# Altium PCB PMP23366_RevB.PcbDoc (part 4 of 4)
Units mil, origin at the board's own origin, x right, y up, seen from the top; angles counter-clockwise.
Board outline 6500 x 4250 mil, 4 copper layers (Top Layer 1, Inner Layer 2, Inner Layer 3, Bottom Layer 1), stack 75.824 mil thick; 370 components, 218 nets, 1221 pads, 351 vias.
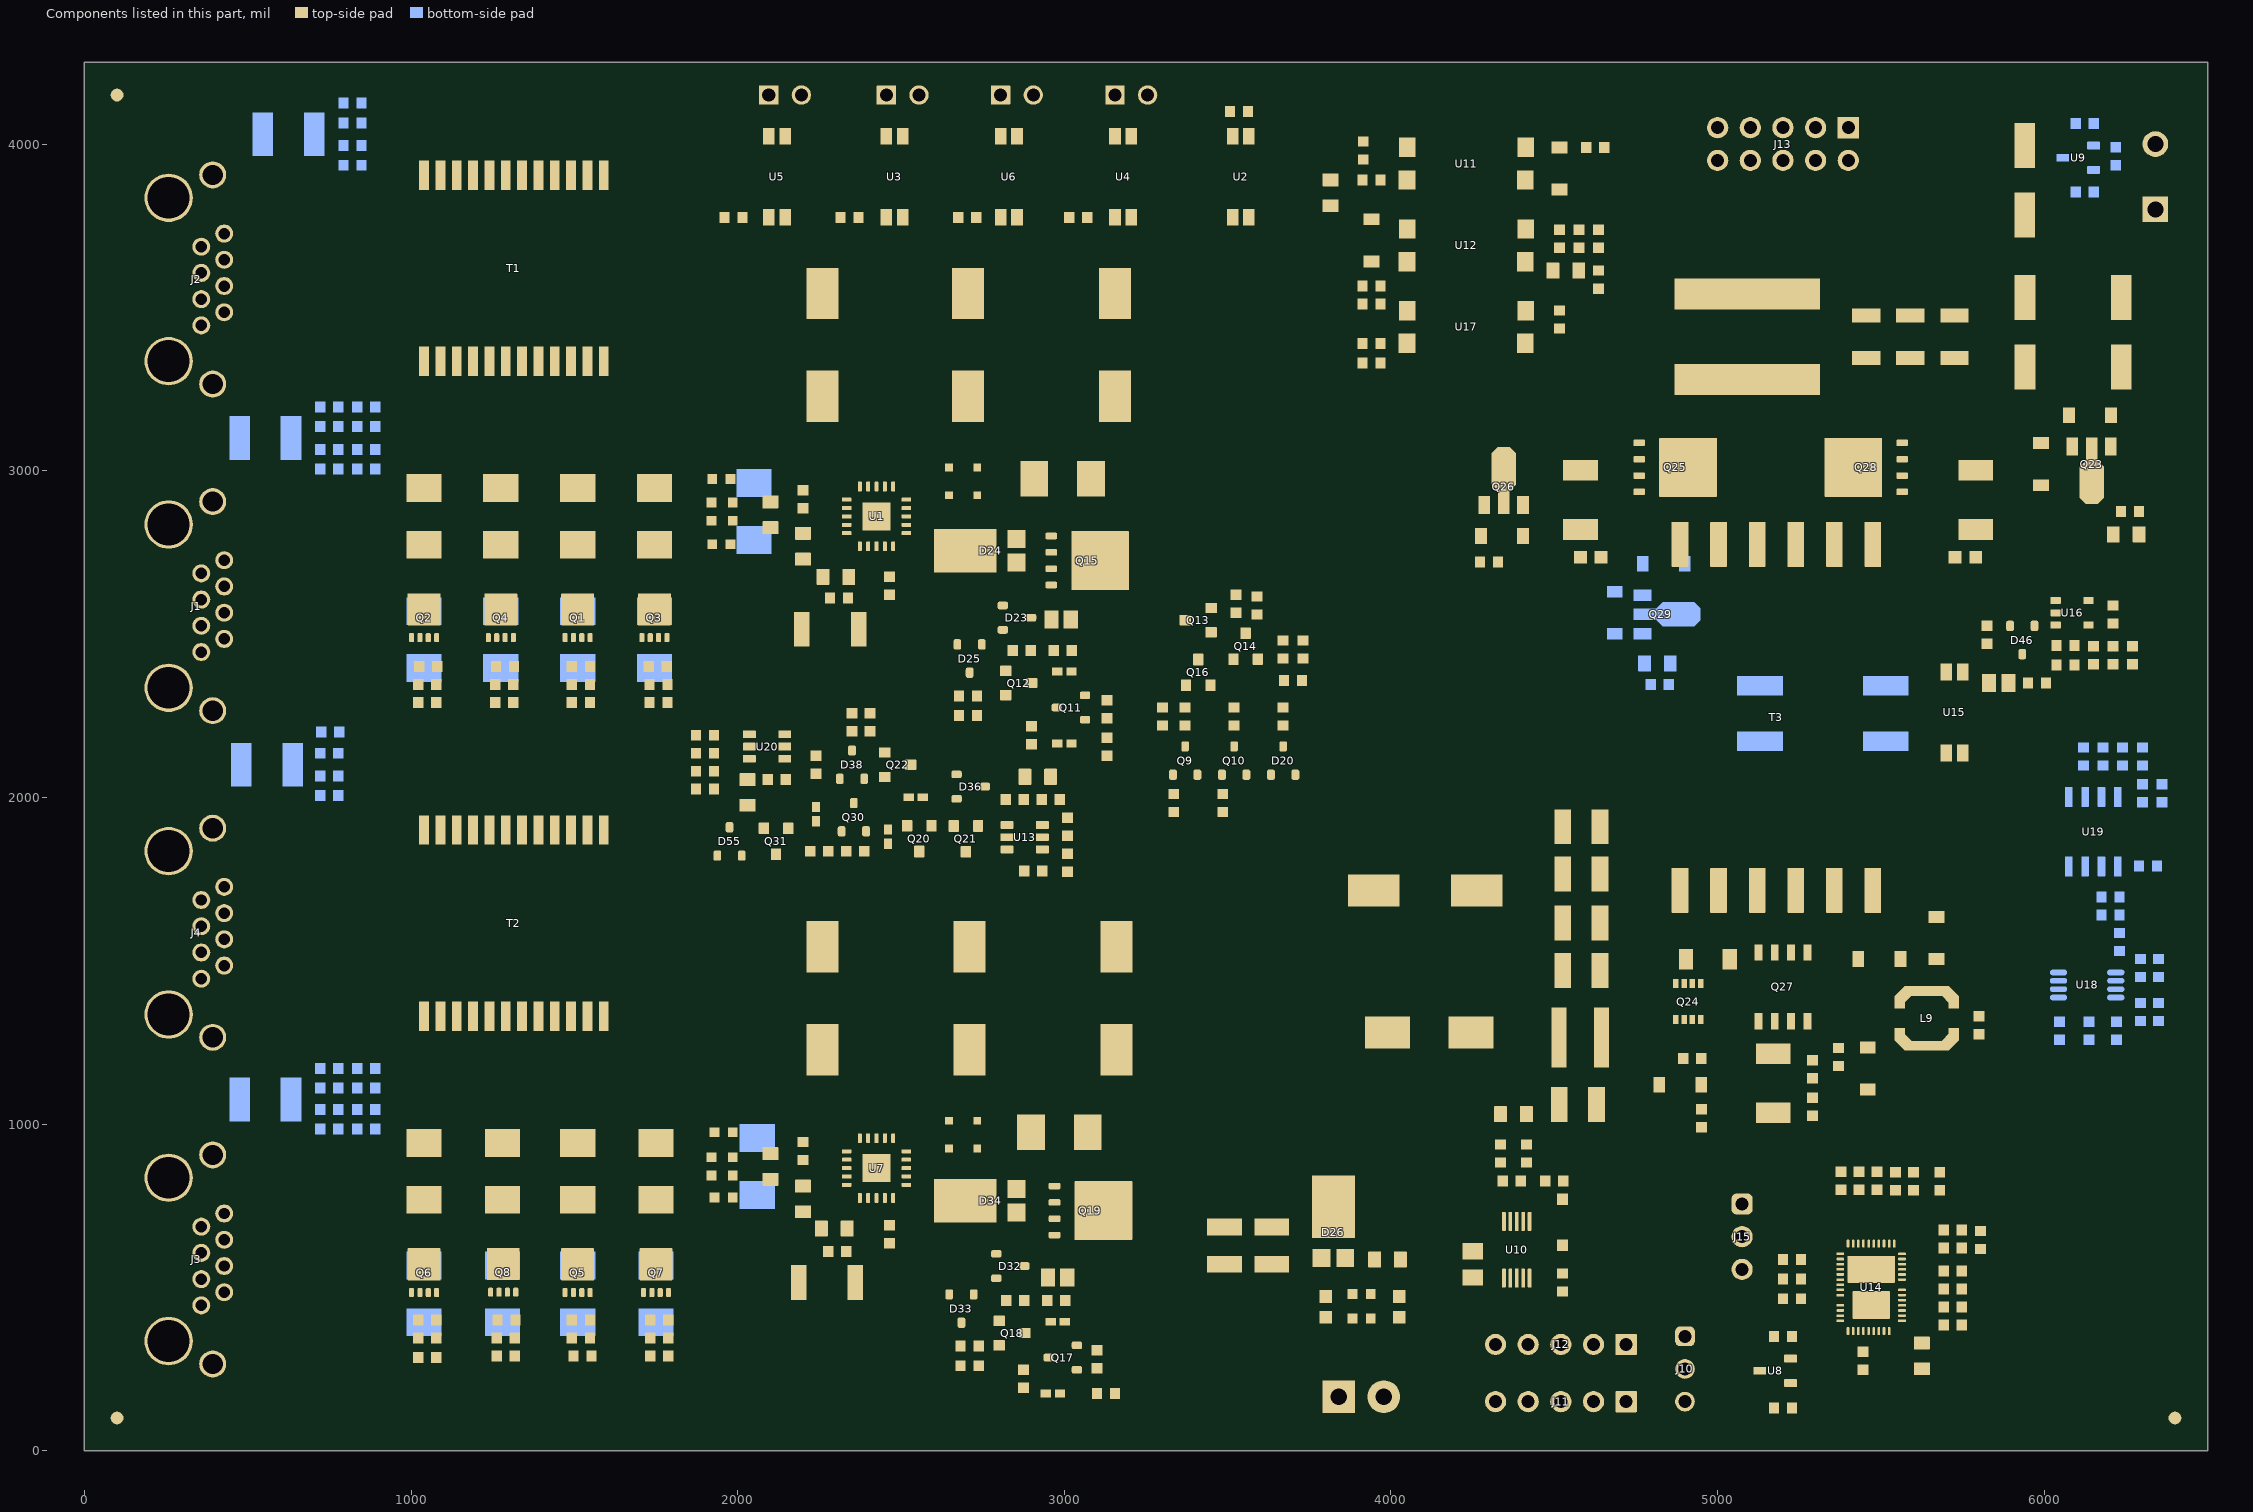
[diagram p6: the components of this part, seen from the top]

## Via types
v1: diameter 34, hole 16, Top Layer 1 to Bottom Layer 1, tented both sides, 307 vias
v2: diameter 19.68, hole 7.87, Top Layer 1 to Bottom Layer 1, 23 vias
v3: diameter 34, hole 16, Top Layer 1 to Bottom Layer 1, 21 vias

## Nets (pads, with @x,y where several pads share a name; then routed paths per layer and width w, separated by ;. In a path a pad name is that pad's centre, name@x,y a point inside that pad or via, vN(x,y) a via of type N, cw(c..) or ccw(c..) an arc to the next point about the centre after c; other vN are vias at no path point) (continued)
pads on no net: D20.2 D23.2 D25.2 D32.2 D33.2 D36.2 D38.2 D55.2 FID1.1 FID2.1 FID3.1 J13.1 J13.2 J13.3 J13.4 J13.7 J13.8 Q1.9@1471.61,2596.26 Q1.9@1483.92,2541.83 Q1.9@1483.92,2577.46 Q1.9@1497.2,2596.26 Q1.9@1510,2562.89 Q1.9@1522.8,2596.26 Q1.9@1536.08,2541.83 Q1.9@1536.08,2577.46 Q1.9@1548.39,2596.26 Q2.9@1001.61,2596.26 Q2.9@1013.92,2541.83 Q2.9@1013.92,2577.46 Q2.9@1027.2,2596.26 Q2.9@1040,2562.89 Q2.9@1052.8,2596.26 Q2.9@1066.08,2541.83 Q2.9@1066.08,2577.46 Q2.9@1078.39,2596.26 Q3.9@1706.61,2596.26 Q3.9@1718.92,2541.83 Q3.9@1718.92,2577.46 Q3.9@1732.2,2596.26 Q3.9@1745,2562.89 Q3.9@1757.8,2596.26 Q3.9@1771.08,2541.83 Q3.9@1771.08,2577.46 Q3.9@1783.39,2596.26 Q4.9@1236.61,2596.26 Q4.9@1248.92,2541.83 Q4.9@1248.92,2577.46 Q4.9@1262.2,2596.26 Q4.9@1275,2562.89 Q4.9@1287.8,2596.26 Q4.9@1301.08,2541.83 Q4.9@1301.08,2577.46 Q4.9@1313.39,2596.26 Q5.9@1471.61,591.26 Q5.9@1483.92,536.83 Q5.9@1483.92,572.46 Q5.9@1497.2,591.26 Q5.9@1510,557.89 Q5.9@1522.8,591.26 Q5.9@1536.08,536.83 Q5.9@1536.08,572.46 Q5.9@1548.39,591.26 Q6.9@1001.61,591.26 Q6.9@1013.92,536.83 Q6.9@1013.92,572.46 Q6.9@1027.2,591.26 Q6.9@1040,557.89 Q6.9@1052.8,591.26 Q6.9@1066.08,536.83 Q6.9@1066.08,572.46 Q6.9@1078.39,591.26 Q7.9@1711.61,591.26 Q7.9@1723.92,536.83 Q7.9@1723.92,572.46 Q7.9@1737.2,591.26 Q7.9@1750,557.89 Q7.9@1762.8,591.26 Q7.9@1776.08,536.83 Q7.9@1776.08,572.46 Q7.9@1788.39,591.26 Q8.9@1243.82,592.28 Q8.9@1256.12,537.85 Q8.9@1256.12,573.48 Q8.9@1269.41,592.28 Q8.9@1282.2,558.92 Q8.9@1295,592.28 Q8.9@1308.29,537.85 Q8.9@1308.29,573.48 Q8.9@1320.59,592.28 Q15.9@3055.04,2667.91 Q15.9@3055.04,2725 Q15.9@3055.04,2782.09 Q15.9@3091.65,2725 Q15.9@3125.12,2667.91 Q15.9@3125.12,2725 Q15.9@3125.12,2782.09 Q19.9@3065.04,677.91 Q19.9@3065.04,735 Q19.9@3065.04,792.09 Q19.9@3101.65,735 Q19.9@3135.12,677.91 Q19.9@3135.12,735 Q19.9@3135.12,792.09 Q25.9@4855.08,2952.91 Q25.9@4855.08,3010 Q25.9@4855.08,3067.09 Q25.9@4891.69,3010 Q25.9@4925.16,2952.91 Q25.9@4925.16,3010 Q25.9@4925.16,3067.09 Q28.9@5399.84,2952.91 Q28.9@5399.84,3010 Q28.9@5399.84,3067.09 Q28.9@5433.31,3010 Q28.9@5469.92,2952.91 Q28.9@5469.92,3010 Q28.9@5469.92,3067.09 U1.10 U1.14 U1.15 U1.16 U1.19 U1.20 U1.21@2401.77,2836.77 U1.21@2401.77,2883.23 U1.21@2448.23,2836.77 U1.21@2448.23,2883.23 U7.10 U7.14 U7.15 U7.16 U7.19 U7.20 U7.21@2401.77,841.77 U7.21@2401.77,888.23 U7.21@2448.23,841.77 U7.21@2448.23,888.23 U13.3 U14.6 U14.10 U14.12 U14.13 U14.14 U14.15 U14.16 U14.18 U14.19 U14.20 U14.21 U14.22 U14.25 U14.26 U14.29 U14.30 U14.36 U14.44 U16.1 U16.2 U20.3

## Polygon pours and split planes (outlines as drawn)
VSS_2 on Top Layer 1 "TOP_LAYER_1_VSS_2_P038" (solid, remove dead copper, pour order 38): 2250,755 2250,825 2270,845 2295,845 2295,400 1970,400 1970,855 2150,855 2150,755
PGND on Top Layer 1 "TOP_LAYER_1_PGND_P072" (solid, remove dead copper, pour order 72): 6450,50 6450,1855 5850,1855 5850,2205 4125,2205 4125,4035 3750,4035 3750,3850 3400,3850 3400,3050 3020,3050 3020,2425 3200,2425 3200,2025 2795,2025 2700,2120 2620,2120 2620,2310 2360,2308.7 2360,2100 2050,2100 2050,1850 3400,1850 3400,1050 3025,1050 3030,1045 3030,635 3030,450 4150,450 4150,50
GND on Top Layer 1 "TOP_LAYER_1_GND_P070" (solid, remove dead copper, pour order 70): 1900,4200 6450,4200 6450,1955 5950,1955 5950,2305 4225,2305 4225,4135 3650,4135 3650,3950 1900,3950
BSVG on Top Layer 1 "TOP_LAYER_1_BSVG_P075" (solid, remove dead copper, pour order 75): 50,50 825,50 825,4200 50,4200
NetC63_2 on Top Layer 1 "TOP_LAYER_1_NETC63_2_P060" (solid, remove dead copper, pour order 60): 5945,3015 5945,2850 6247.97,2850 6247.97,3015
VOUT on Top Layer 1 "TOP_LAYER_1_VOUT_P058" (solid, remove dead copper, pour order 58): 4825,3450 6450,3450 6450,3875 5800,3875 5800,3700 4825,3700
NetC63_2 on Top Layer 1 "TOP_LAYER_1_NETC63_2_P057" (solid, remove dead copper, pour order 57): 5150,2700 5150,3165 5350,3165 5350,3375 4825,3375 4825,2700
NetC73_1 on Top Layer 1 "TOP_LAYER_1_NETC73_1_P056" (solid, remove dead copper, pour order 56): 5500,3125 5210,3125 5210,2700 5500,2700
VCC on Top Layer 1 "TOP_LAYER_1_VCC_P055" (solid, remove dead copper, pour order 55): 5535,1300 5745,1300 5745,1200 5535,1200
NetD44_1 on Top Layer 1 "TOP_LAYER_1_NETD44_1_P054" (solid, remove dead copper, pour order 54): 5745,1350 5745,1550 5535,1550 5535,1350
AUX on Top Layer 1 "TOP_LAYER_1_AUX_P053" (solid, remove dead copper, pour order 53): 3895,550 3970,550 3970,615 3745,615 3745,450 3895,450
NetC40_1 on Top Layer 1 "TOP_LAYER_1_NETC40_1_P052" (solid, remove dead copper, pour order 52): 3895,100 3895,425 3770,425 3770,100
NetC40_2 on Top Layer 1 "TOP_LAYER_1_NETC40_2_P051" (solid, remove dead copper, pour order 51): 3925,100 3925,425 4050,425 4045,420 4045,100
NetQ27_1 on Top Layer 1 "TOP_LAYER_1_NETQ27_1_P048" (solid, remove dead copper, pour order 48): 5235,1340 5235,1165 5100,1165 5100,1340
NetC64_1 on Top Layer 1 "TOP_LAYER_1_NETC64_1_P047" (solid, remove dead copper, pour order 47): 4975,1360 4974.9,1554.9 4975,1555 4875,1555 4845,1525 4845,1360
NetC64_2 on Top Layer 1 "TOP_LAYER_1_NETC64_2_P046" (solid, remove dead copper, pour order 46): 5325,1375 5325,1555 5300,1555 5300,1800 5065,1800 5065,1555 5015,1555 5015,1375
NetC59_1 on Top Layer 1 "TOP_LAYER_1_NETC59_1_P045" (solid, remove dead copper, pour order 45): 4750,1500 4800,1550 4875,1625 5035,1625 5035,1970 5030,1975 4600,1975 4600,1155 4750,1155
VDD_PM on Top Layer 1 "TOP_LAYER_1_VDD_PM_P044" (solid, remove dead copper, pour order 44): 4395,925 4550,925 4550,1375 4395,1375 4395,1100
NetC42_2 on Top Layer 1 "TOP_LAYER_1_NETC42_2_P043" (solid, remove dead copper, pour order 43): 2825,700 2825,1050 2985,1050 2985,700
NetC28_2 on Top Layer 1 "TOP_LAYER_1_NETC28_2_P042" (solid, remove dead copper, pour order 42): 2975,2690 2825.06,2689.94 2825,2690 2825,3050 2975,3050
RTN1 on Top Layer 1 "TOP_LAYER_1_RTN1_P041" (solid, remove dead copper, pour order 41): 2525,2950 2205,2950 2205,3375 3340,3375 3340,3100 2790,3100 2790,2650 2525,2650
RTN2 on Top Layer 1 "TOP_LAYER_1_RTN2_P040" (solid, remove dead copper, pour order 40): 2525,950 2200,950 2200,1375 3350,1375 3350,1100 2790,1100 2790,675 2525,675
VSS_1 on Top Layer 1 "TOP_LAYER_1_VSS_1_P039" (solid, remove dead copper, pour order 39): 2250,2810 2280,2840 2305,2840 2305,2455 1965,2455 1965,2845 1960,2850 2150,2850 2150,2750 2250,2750
NetC1_2 on Top Layer 1 "TOP_LAYER_1_NETC1_2_P031" (solid, remove dead copper, pour order 31): 1605,2325 1745,2325 1745,2430 1765,2450 1765,2500 1605,2500
NetC1_2 on Top Layer 1 "TOP_LAYER_1_NETC1_2_P030" (solid, remove dead copper, pour order 30): 1370,2325 1510,2325 1510,2430 1530,2450 1530,2500 1370,2500
NetC1_2 on Top Layer 1 "TOP_LAYER_1_NETC1_2_P029" (solid, remove dead copper, pour order 29): 1135,2325 1275,2325 1275,2430 1295,2450 1295,2500 1135,2500
NetC1_2 on Top Layer 1 "TOP_LAYER_1_NETC1_2_P028" (solid, remove dead copper, pour order 28): 900,2325 900.67,2324.33 1040,2324.33 1040,2430 1060,2450 1060,2500 900,2500
NetC13_2 on Top Layer 1 "TOP_LAYER_1_NETC13_2_P027" (solid, remove dead copper, pour order 27): 1610,325 1750,325 1750,435 1770,455 1770,495 1610,495
NetC13_2 on Top Layer 1 "TOP_LAYER_1_NETC13_2_P026" (solid, remove dead copper, pour order 26): 1370,325 1370,495 1530,495 1530,455 1510,435 1510,325
NetC13_2 on Top Layer 1 "TOP_LAYER_1_NETC13_2_P025" (solid, remove dead copper, pour order 25): 1139.43,322.78 1277.78,322.78 1280,325 1280,435 1300,455 1300,495 1140,495
NetC13_2 on Top Layer 1 "TOP_LAYER_1_NETC13_2_P023" (solid, remove dead copper, pour order 23): 1060,495 1060,455 1040,435 1040,325 900,325 900,495
NetC13_2 on Top Layer 1 "TOP_LAYER_1_NETC13_2_P022" (solid, remove dead copper, pour order 22): 1865,860 1945,860 1945,575 1865,575
NetC1_2 on Top Layer 1 "TOP_LAYER_1_NETC1_2_P021" (solid, remove dead copper, pour order 21): 1860,2625 1860,2860 1940,2860 1940,2625
PR78_1 on Top Layer 1 "TOP_LAYER_1_PR78_1_P010" (solid, remove dead copper, pour order 10): 1130,2530 1130,2835 950,2835 950,2530
PR45_1 on Top Layer 1 "TOP_LAYER_1_PR45_1_P009" (solid, remove dead copper, pour order 9): 1365,2530 1365,2835 1185,2835 1185,2530
PR36_1 on Top Layer 1 "TOP_LAYER_1_PR36_1_P008" (solid, remove dead copper, pour order 8): 1600,2530 1600,2835 1420,2835 1421.42,2833.58 1421.42,2530
PR12_1 on Top Layer 1 "TOP_LAYER_1_PR12_1_P007" (solid, remove dead copper, pour order 7): 1835,2530 1835,2835 1655,2835 1655,2530
PR12_2 on Top Layer 1 "TOP_LAYER_1_PR12_2_P006" (solid, remove dead copper, pour order 6): 1840,830 1840,525 1660,525 1660,830
PR36_2 on Top Layer 1 "TOP_LAYER_1_PR36_2_P005" (solid, remove dead copper, pour order 5): 1600,830 1600,525 1420,525 1420,830
PR45_2 on Top Layer 1 "TOP_LAYER_1_PR45_2_P004" (solid, remove dead copper, pour order 4): 1190,830 1190,525 1370,525 1370,830
PR78_2 on Top Layer 1 "TOP_LAYER_1_PR78_2_P003" (solid, remove dead copper, pour order 3): 950,525 950,830 1130,830 1130,525
NetC1_1 on Top Layer 1 "TOP_LAYER_1_NETC1_1_P002" (solid, remove dead copper, pour order 2): 960,3050 1940,3050 1940,2885 960,2885
NetC13_1 on Top Layer 1 "TOP_LAYER_1_NETC13_1_P001" (solid, remove dead copper, pour order 1): 960,1050 1945,1050 1945,885 960,885
VDD on Top Layer 1 "TOP_LAYER_1_VDD_P000" (solid, remove dead copper, pour order 0): 4250,700 4250,1000 4355,1000 4355,1100 4125,1100 4125,2925 3800,3250 3800,3700 1900,3700 1900,3075 1965,3075 1965,2885 2150,2885 2150,3425 3400,3425 3400,3050 3035,3050 3035,2900 3550,2900 3800,2650 3800,2050 3450,1700 1900,1700 1900,1100 1970,1100 1970,885 2150,885 2150,1425 3400,1425 3400,1050 3025,1050 3025,900 3400,900 3400,650 3865,650 3865,700
RTN1 on Bottom Layer 1 "BOTTOM_LAYER_1_RTN1_P080" (solid, remove dead copper, pour order 80): 1775,1800 2180,1800 2180,2310 2050,2310 2050,2250 1900,2250 1865,2215 1775,2215
NetC28_2 on Bottom Layer 1 "BOTTOM_LAYER_1_NETC28_2_P074" (solid, remove dead copper, pour order 74): 2655,2150 2655,2370 2625,2370 2625,2500 2700,2500 2700,2600 2825,2600 2825,3050 2975,3050 2975,2375 3150,2375 3150,2150
PAD_S on Bottom Layer 1 "BOTTOM_LAYER_1_PAD_S_P081" (solid, remove dead copper, pour order 81): 5530,400 5530,490 5410,490 5410,400
RTN1 on Bottom Layer 1 "BOTTOM_LAYER_1_RTN1_P078" (solid, remove dead copper, pour order 78): 2525,2650 2525,2950 2205,2950 2205,3150 1900,3150 1900,3850 3340,3850 3340,3100 2790,3100 2790,2650
RTN2 on Bottom Layer 1 "BOTTOM_LAYER_1_RTN2_P077" (solid, remove dead copper, pour order 77): 2790,675 2790,1100 3350,1100 3345,1105 3345,1700 1900,1700 1900,1150 2200,1150 2200,950 2525,950 2525,675
NetC42_2 on Bottom Layer 1 "BOTTOM_LAYER_1_NETC42_2_P071" (solid, remove dead copper, pour order 71): 2600,150 2598.01,548.01 2600,550 2700,550 2700,630 2825,630 2825,1050 2985,1050 2985,405 2980,400 3200,400 3200,150
PGND on Bottom Layer 1 "BOTTOM_LAYER_1_PGND_P088" (solid, remove dead copper, pour order 88): 3200,1850 3200,1750 2750,1750 2750,1800 2225,1800 2225,2310 2620,2310 2620,2130 3200,2130 3200,2425 3020,2425 3020,3050 3400,3050 3400,3850 3750,3850 3750,4035 4125,4035 4125,2205 5850,2205 5850,1855 6450,1855 6450,50 4150,50 4150,450 3030,450 3030,1045 3025,1050 3400,1050 3400,1850
GND on Bottom Layer 1 "BOTTOM_LAYER_1_GND_P082" (solid, remove dead copper, pour order 82): 6450,1955 6450,4200 1900,4200 1900,3950 3650,3950 3650,4135 4225,4135 4225,2305 5950,2305 5950,1955
BSVG on Bottom Layer 1 "BOTTOM_LAYER_1_BSVG_P090" (solid, remove dead copper, pour order 90): 825,50 825,4200 50,4200 50,50
NetC59_1 on Bottom Layer 1 "BOTTOM_LAYER_1_NETC59_1_P061" (solid, remove dead copper, pour order 61): 5055,2205 5055,2050 4900,2050 4900,1925 5205,1925 5205,2205
NetC73_1 on Bottom Layer 1 "BOTTOM_LAYER_1_NETC73_1_P059" (solid, remove dead copper, pour order 59): 4835,2325 5000,2325 5000,2625 4835,2625
VSS_2 on Bottom Layer 1 "BOTTOM_LAYER_1_VSS_2_P037" (solid, remove dead copper, pour order 37): 2235,855 2250,870 2380,870 2380,910 2485,910 2485,400 1970,400 1970,855
VDD on Bottom Layer 1 "BOTTOM_LAYER_1_VDD_P035" (solid, remove dead copper, pour order 35): 2150,1100 2150,885 1970,885 1970,1100
VSS_1 on Bottom Layer 1 "BOTTOM_LAYER_1_NONET_P034" (solid, remove dead copper, pour order 34): 2234.78,2850 2249.98,2865.2 2250.17,2865 2380,2865 2380,2905 2485,2905 2485,2455 1965,2455 1965,2850
VDD on Bottom Layer 1 "BOTTOM_LAYER_1_VDD_P033" (solid, remove dead copper, pour order 33): 2150,3100 2150,2885 1965,2885 1965,3100
NetC1_2 on Bottom Layer 1 "BOTTOM_LAYER_1_NETC1_2_P020" (solid, remove dead copper, pour order 20): 900,2500 1860,2500 1860,2860 1940,2860 1940,2325 900,2325
NetC13_2 on Bottom Layer 1 "BOTTOM_LAYER_1_NETC13_2_P019" (solid, remove dead copper, pour order 19): 1945,860 1945,325 900,325 900,495 1865,495 1865,860
PR78_1 on Bottom Layer 1 "BOTTOM_LAYER_1_PR78_1_P018" (solid, remove dead copper, pour order 18): 1128.11,2528.65 1130,2530.54 1130,2725 950,2725 950,2530
PR45_1 on Bottom Layer 1 "BOTTOM_LAYER_1_PR45_1_P017" (solid, remove dead copper, pour order 17): 1365,2530 1365,2725 1185,2725 1185,2530
PR36_1 on Bottom Layer 1 "BOTTOM_LAYER_1_PR36_1_P016" (solid, remove dead copper, pour order 16): 1600,2530 1600,2725 1420,2725 1420,2530
PR12_1 on Bottom Layer 1 "BOTTOM_LAYER_1_PR12_1_P015" (solid, remove dead copper, pour order 15): 1835,2530 1835,2725 1655,2725 1655,2530
PR12_2 on Bottom Layer 1 "BOTTOM_LAYER_1_PR12_2_P014" (solid, remove dead copper, pour order 14): 1660,525 1660,725 1840,725 1840,525
PR36_2 on Bottom Layer 1 "BOTTOM_LAYER_1_PR36_2_P013" (solid, remove dead copper, pour order 13): 1420,525 1420,725 1600,725 1600,525
PR45_2 on Bottom Layer 1 "BOTTOM_LAYER_1_PR45_2_P012" (solid, remove dead copper, pour order 12): 1190,725 1190,525 1370,525 1370,725
PR78_2 on Bottom Layer 1 "BOTTOM_LAYER_1_PR78_2_P011" (solid, remove dead copper, pour order 11): 950,525 950,725 1130,725 1130,525
RTN1 on Inner Layer 2 "INNER_LAYER_2_RTN1_P066" (solid, remove dead copper, pour order 66): 1775,1800 2180,1800 2180,2350 2575,2350 2575,2575 2650,2575 2650,2720 2525,2720 2525,2400 2050,2400 2050,2250 1900,2250 1865,2215 1775,2215
PGND on Inner Layer 2 "INNER_LAYER_2_PGND_P091" (solid, remove dead copper, pour order 91): 3202.5,1847.5 3202.5,1750 2750,1750 2750,1800 2225,1800 2225,2310 2620,2310 2620,2127.5 2632.5,2127.5 3202.5,2127.5 3202.5,2422.5 3022.5,2422.5 3022.5,3047.5 3402.5,3047.5 3402.5,3847.5 3752.5,3847.5 3752.5,4032.5 4127.5,4032.5 4127.5,2202.5 5852.5,2202.5 5852.5,1852.5 6452.5,1852.5 6452.5,47.5 4152.5,47.5 4152.5,447.5 3032.5,447.5 3032.5,1047.5 3402.5,1047.5 3402.5,1847.5
NetC28_2 on Inner Layer 2 "INNER_LAYER_2_NETC28_2_P062" (solid, remove dead copper, pour order 62): 3150,2375 2975,2375 2975,3050 2825,3050 2825,2605 2830,2600 2700,2600 2700,2500 2625,2500 2625,2370 2655,2370 2655,2150 3150,2150
VSS_2 on Inner Layer 2 "INNER_LAYER_2_VSS_2_P068" (solid, remove dead copper, pour order 68): 2150,910 2150,1100 1970,1100 1970,400 2485.47,398.68 2485.47,909.53 2485,910
VSS_1 on Inner Layer 2 "INNER_LAYER_2_VSS_1_P067" (solid, remove dead copper, pour order 67): 2150,2905 2150,3100 1965,3100 1965,2455 2485,2455 2485,2905
RTN2 on Inner Layer 2 "INNER_LAYER_2_RTN2_P065" (solid, remove dead copper, pour order 65): 2200,1150 1900,1150 1900,1700 3350,1700 3350,1100 2790,1100 2790,675 2525,675 2525,950 2200,950
NetC42_2 on Inner Layer 2 "INNER_LAYER_2_NONET_P066" (solid, remove dead copper, pour order 64): 3200,400 2985,400 2985,1050 2825,1050 2825,630 2700,630 2700,550 2600,550 2600,150 3200,150
RTN1 on Inner Layer 2 "INNER_LAYER_2_RTN1_P063" (solid, remove dead copper, pour order 63): 2791.61,2650.65 2790,2652.26 2790,3100 3340,3100 3340,3110 3340,3850 1900,3850 1900,3150 2205,3150 2205,2950 2525,2950 2525,2650
GND on Inner Layer 2 "INNER_LAYER_2_GND_P069" (solid, remove dead copper, pour order 69): 4225,4135 3650,4135 3650,3950 1900,3950 1900,4200 6450,4200 6450,1955 5950,1955 5950,2305 4225,2305
RTN1 on Inner Layer 3 "INNER_LAYER_3_RTN1_P083" (solid, remove dead copper, pour order 83): 2575,2575 2650,2575 2650,2715 2525,2715 2525,2400 2050,2400 2050,2250 1900,2250 1865,2215 1775,2215 1775,1800 2180,1800 2180,2350 2575,2350
RTN1 on Inner Layer 3 "INNER_LAYER_3_RTN1_P086" (solid, remove dead copper, pour order 86): 2525,2650 2525,2950 2205,2950 2205,3150 1900,3150 1900,3850 3340,3850 3340,3100 2790,3100 2790,2650
NetC28_2 on Inner Layer 3 "INNER_LAYER_3_NETC28_2_P085" (solid, remove dead copper, pour order 85): 3150,2150 3150,2375 2975,2375 2975,3050 2825,3050 2825,2600 2700,2600 2700,2500 2625,2500 2625,2370 2655,2370 2655,2150
VSS_1 on Inner Layer 3 "INNER_LAYER_3_VSS_1_P084" (solid, remove dead copper, pour order 84): 2485,2455 2485,2905 2150,2905 2150,3100 1965,3100 1965,2455.49 1965.49,2455
RTN2 on Inner Layer 3 "INNER_LAYER_3_RTN2_P079" (solid, remove dead copper, pour order 79): 2790,675 2790,1100 3350,1100 3350,1700 1900,1700 1900,1150 2200,1150 2200,950 2525,950 2525,675
VSS_2 on Inner Layer 3 "INNER_LAYER_3_VSS_2_P076" (solid, remove dead copper, pour order 76): 2485,400 2485,910 2150,910 2150,1100 1970,1100 1970,400
NetC42_2 on Inner Layer 3 "INNER_LAYER_3_NETC42_2_P073" (solid, remove dead copper, pour order 73): 3200,150 3200,400 2985,400 2985,1050 2825,1050 2825,630 2700,630 2700,550 2600,550 2600,150
PGND on Inner Layer 3 "INNER_LAYER_3_PGND_P089" (solid, remove dead copper, pour order 89): 3200,2120 2620,2120 2620,2310 2225,2310 2225,1805 2220,1800 2750,1800 2750,1750 3200,1750 3200,1850 3400,1850 3400,1050 3025,1050 3030,1045 3030,450 4150,450 4150,50 6450,50 6450,1855 5850,1855 5850,2205 4125,2205 4125,4035 3750,4035 3750,3850 3400,3850 3400,3050 3020,3050 3020,2425 3200,2425
GND on Inner Layer 3 "INNER_LAYER_3_GND_P087" (solid, remove dead copper, pour order 87): 6450,1955 5950,1955 5950,2305 4225,2305 4225,4135 3650,4135 3650,3950 1900,3950 1900,4200 6450,4200

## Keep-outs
Keep-Out Layer:
  text ".Layer_Name" at 577,-858.49 h60

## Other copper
Top Layer 1:
  rectangle net NetC63_2: 6125,3025 6165,3040
  rectangle net GND: 4325,2930.78 4365,2950
  rectangle net RTN1: 2502.32,2800 2599.45,2840.49
  rectangle net RTN2: 2501.39,795 2600,846.55
  rectangle net VSS_2: 2270,805 2345,845
  rectangle net VSS_1: 2280,2800 2350,2840
  text ".Layer_Name" at 577,-858.49 h60
Bottom Layer 1:
  rectangle net NetC73_1: 4805,2540 4825,2580
  text ".Layer_Name" at 577,-858.49 h60

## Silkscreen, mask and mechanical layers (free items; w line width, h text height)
Top Overlay:
  lines w10: 4448.31,3780 4578,3780 4603,3805 4730,3805
  text "'.PRJ_Number'.PCB_Rev" at 6170.67,1496.42 h108.27 r90
  text ".Layer_Name" at 577,-858.49 h60
Bottom Overlay:
  text ".Layer_Name" at 577,-858.49 h60
Top Paste:
  text ".Layer_Name" at 577,-858.49 h60
Bottom Paste:
  text ".Layer_Name" at 577,-858.49 h60
Top Solder:
  text ".Layer_Name" at 577,-858.49 h60
  text ".Layer_Name" at 577,-858.49 h60
Bottom Solder:
  text ".Layer_Name" at 577,-858.49 h60
Drill Guide:
  text ".Layer_Name" at 577,-858.49 h60
M1 Board Outline:
  the board outline again, w10
  text ".Layer_Name" at 577,-858.49 h60
M2 Board Dimensions:
  rectangle: 0,-275 125,-150
  rectangle: 125,-400 500,-275
  lines w7: 0,-275 1000,-275 ; 125,-400 125,-150 ; 250,-400 250,-150 ; 500,-400 500,-150 ; 750,-400 750,-150 ; 0,-400 1000,-400 1000,-150 0,-150 0,-400
  text ".Layer_Name" at 577,-858.49 h60
M3 3D STEP Top:
  text ".Layer_Name" at 577,-858.49 h60
M4 3D STEP Bottom:
  text ".Layer_Name" at 577,-858.49 h60
M5 Assembly Top:
  lines w10: -292,-930.17 6308,-930.17 ; -292,-726.83 6310,-726.83 ; -292,-523.5 -292,-1133.5 3713,-1133.5 6310,-1133.5 6310,-523.5 -291.5,-523.5 -291.5,-1133.5 1284,-1133.5 ; 2173,-1133.5 2173,-523.5 ; 3440,-726.83 3440,-523.5 ; 4280,-726.83 4280,-523.5 ; 4902,-1140 4902,-937.17
  text "COMPONENTS MARKED 'DNP' SHOULD NOT BE POPULATED." at 1153.5,-318.5 h60
  text "ASSEMBLY VARIANT:" at 1153,-434 h60
  text ".VariantName" at 2189,-434 h60
  text "PCB VIEWED FROM TOP SIDE" at -228.5,-655.67 h60
  text "BOARD #:" at 2248,-655.67 h60
  text ".PRJ_Number" at 2793.5,-655.67 h60
  text "REV:" at 3638,-655.67 h60
  text ".PCB_Rev" at 3929.5,-655.67 h60
  text "SVN REV:" at 4476,-655.67 h60
  text ".VersionControl_RevNumber" at 4982,-655.67 h60
  text "TID #:" at 2248,-859 h60
  text ".TID" at 2793.5,-859 h60
  text "PLOT NAME =" at -228.5,-1064.34 h60
  text ".plot_File_Name" at 577,-1064.34 h60
  text "GENERATED    :" at 2250,-1064.34 h60
  text ".Print_Date" at 3119.5,-1064.34 h60
  text ".Print_Time" at 3848.5,-1064.34 h60
  text "TEXAS INSTRUMENTS" at 5113,-1064.34 h60
M6 Assembly Bottom:
  lines w10: -292.5,-727.33 6309.5,-727.33 ; -290.5,-930.67 6309.5,-930.67 ; 1115.5,-1140.5 1115.5,-937.67 ; 1737.5,-727.33 1737.5,-524 ; 2577.5,-727.33 2577.5,-524 ; 3844.5,-1134 3844.5,-524 ; 4733.5,-1134 6309,-1134 6309,-524 -292.5,-524 -292.5,-1134 2304.5,-1134 6309.5,-1134 6309.5,-524
  text "COMPONENTS MARKED 'DNP' SHOULD NOT BE POPULATED." at 6102,-318 h60
  text ".VariantName" at 5058,-434 h60
  text "ASSEMBLY VARIANT:" at 6097,-434 h60
  text ".VersionControl_RevNumber" at 1035.5,-656.17 h60
  text "SVN REV:" at 1541.5,-656.17 h60
  text ".PCB_Rev" at 2088,-656.17 h60
  text "REV:" at 2379.5,-656.17 h60
  text ".PRJ_Number" at 3224,-656.17 h60
  text "BOARD #:" at 3769.5,-656.17 h60
  text "PCB VIEWED FROM BOTTOM SIDE" at 6246,-656.17 h60
  text ".TID" at 3224,-859.5 h60
  text "TID #:" at 3769.5,-859.5 h60
  text "TEXAS INSTRUMENTS" at 904.5,-1064.84 h60
  text ".Print_Time" at 2169,-1064.84 h60
  text ".Print_Date" at 2898,-1064.84 h60
  text "GENERATED    :" at 3767.5,-1064.84 h60
  text ".plot_File_Name" at 5440.5,-1064.84 h60
  text "PLOT NAME =" at 6246,-1064.84 h60
M9 Title Sheet:
  drawing of 57 lines, arcs and shapes, not listed
  text "1" at 739.84,8036.5 h70
  text "2" at 3235.5,8036.5 h70
  text "3" at 5724.84,8036.5 h70
  text "4" at 8231.51,8036.5 h70
  text "5" at 10730.5,8036.5 h70
  text "6" at 13235.5,8036.5 h70
  text "A" at -416.5,6893.5 h70
  text "A" at 14383.5,6893.5 h70
  text "B" at -416.5,4513.5 h70
  text "B" at 14383.5,4513.5 h70
  text "C" at -416.5,2138.5 h70
  text "C" at 14383.5,2138.5 h70
  text "PROJECT TITLE:" at 11343.5,277.5 h45
  text ".PRJ_Title" at 11393.5,144.17 h70
  text "DESIGNED FOR:" at 11343.5,-23.5 h45
  text ".PRJ_Customer" at 11393.5,-163.5 h70
  text "D" at -416.5,-231.5 h70
  text "D" at 14383.5,-231.5 h70
  text "FILE NAME:" at 11343.5,-323.5 h45
  text ".PCB_File_Name_No_Path" at 11393.5,-443.5 h70
  text "Texas Instruments (TI) and/or its licensors do not warrant the accuracy or completeness of this specification" at 6374,-605.34 h45
  text "ENGINEER:" at 11343.5,-613.5 h45
  text "LAYOUT BY:" at 12848.5,-613.5 h45
  text "or any information contained therein. TI and/or its licensors do not warrant that this design will meet" at 6329.01,-718 h45
  text ".PRJ_Engineer" at 11393.5,-768.49 h70
  text ".PCB_Layout" at 12899,-768.49 h70
  text "the specifications, will be suitable for your application or fit for any particular purpose, or will operate in" at 6329.01,-830.67 h45
  text ".Layer_Name" at 577,-858.49 h60
  text "ALTIUM DESIGNER VERSION:" at 12848.5,-923.5 h45
  text "an implementation. TI and/or its licensors do not warrant that the design is production worthy. You should" at 6329.01,-943.33 h45
  text "completely validate and test your design implementation to confirm the system functionality for your application." at 6374,-1056 h45
  text ".print_Scale" at 11393.5,-1056.83 h70
  text ".Application_BuildNumber" at 12899,-1056.83 h70
  text "1" at 739.84,-1263.5 h70
  text "2" at 3235.5,-1263.5 h70
  text "3" at 5724.84,-1263.5 h70
  text "4" at 8231.51,-1263.5 h70
  text "5" at 10730.5,-1263.5 h70
  text "6" at 13235.5,-1263.5 h70
M10 Fab Notes:
  drawing of 189 lines, arcs and shapes, not listed
  text "DESIGN INFORMATION" at 12382.02,6356.17 h60
  text "MIN. TRACK WIDTH:" at 11737.46,6224.05 h60
  text "8" at 12833.7,6224.05 h60
  text "MIL" at 12988.46,6224.05 h60
  text "7.874" at 12667.32,6102.36 h60
  text "MIN. CLEARANCE:" at 11737.46,6099.92 h60
  text "MIL" at 12988.46,6099.92 h60
  text "MIN. VIA PAD SIZE:" at 11737.46,5975.8 h60
  text "24" at 12803.71,5975.8 h60
  text "MIL" at 12988.46,5975.8 h60
  text "0.05mm (2MIL)" at 12432.46,5845.9 h60
  text "MINIMUM ANNULAR RING" at 11408.23,5837.67 h60
  text "EXTERNAL" at 13140.46,5837.67 h60
  text "PER" at 11608.23,5727.55 h60
  text "IPC-D-275 CLASS 2 LEVEL C" at 11828.23,5727.54 h60
  text "MIL, HOLES" at 13316.46,5627.07 h60
  text "+/-" at 12924,5618.48 h60
  text "+/-" at 13778,5618.48 h60
  text "REGISTRATION TOLERANCES:" at 11408.23,5617.42 h60
  text "METAL" at 12608,5617.42 h60
  text "5" at 13184.2,5617.42 h60
  text "3" at 14017.2,5617.42 h60
  text "MIL" at 14133.46,5617.42 h60
  text "HOLE SIZE TOLERANCE (UNLESS OTHERWISE SPECIFIED):" at 11408.23,5519.1 h60
  text "+/-" at 13778,5516.23 h60
  text "3" at 14017.2,5515.17 h60
  text "MIL" at 14133.46,5515.17 h60
  text "MATERIAL:" at 11333.46,5377.52 h60
  text "FR-4 High Tg" at 12319.9,5249 h60
  text "X" at 12175.46,5241.01 h60
  text "FR-4" at 11754.46,5236.49 h60
  text "OTHER" at 13242.46,5236.49 h60
  text "62 MIL (1.6mm) +/-10%" at 12074.56,5093.46 h60
  text "X" at 11954.46,5091.01 h60
  text "THICKNESS:" at 11408.23,5085.24 h60
  text "OTHER" at 13359.46,5085.24 h60
  text "TOLERANCE:" at 11408.23,4946.92 h60
  text "X" at 12256.46,4946.92 h60
  text "ANSI IPC-6012 TYPE 3 CLASS 2" at 12434.48,4946.92 h60
  text "OTHER +/-" at 12434.46,4802.73 h60
  text "BOW & TWIST:" at 11408.23,4657.54 h60
  text "X" at 12256.46,4657.54 h60
  text "ANSI IPC-6012 TYPE 3 CLASS 2" at 12434.48,4657.54 h60
  text "OTHER +/-" at 12434.46,4510.85 h60
  text "DRILLING:" at 11333.46,4380.23 h60
  text "NC_DRILL FILES" at 13094.46,4275.04 h60
  text "REFERENCE:" at 11408.23,4271.1 h60
  text "X" at 12065.46,4271.01 h60
  text "AS SHOWN" at 12243.46,4271.1 h60
  text "X" at 12966.46,4271.1 h60
  text "OTHER" at 13392.46,4128.85 h60
  text "PTH COPPER THICKNESS:" at 11407.91,4125.32 h60
  text "X" at 12547.14,4125.32 h60
  text "20-30 um" at 12675.14,4125.32 h60
  text "BOARD FINISH:" at 11333.46,3977.73 h60
  text "SILKSCREEN:" at 11488.68,3867.6 h60
  text "X" at 12446.46,3867.6 h60
  text "TOP" at 12563.46,3867.6 h60
  text "X" at 12956.46,3867.6 h60
  text "BOTTOM" at 13074.46,3867.6 h60
  text "SILKSCREEN COLOR:" at 11488.68,3712.41 h60
  text "X" at 12445.46,3712.41 h60
  text "WHITE" at 12563.46,3712.41 h60
  text "OTHER" at 13074.46,3712.41 h60
  text "X" at 12576.46,3568.96 h60
  text "GREEN" at 12694.46,3568.96 h60
  text "OTHER" at 13312.46,3568.96 h60
  text "SOLDER RESIST COLOR:" at 11488.68,3562.1 h60
  text "X" at 12576.46,3414.71 h60
  text "MATTE" at 12694.46,3414.71 h60
  text "SEMI-GLOSS" at 13312,3414.07 h60
  text "IMMERSION GOLD (ENIG)" at 12394.46,3241.94 h60
  text "ENEPIG" at 13732,3234.72 h60
  text "SURFACE FINISH:" at 11333.46,3233.72 h60
  text "X" at 12216.46,3233.72 h60
  text "IMM. TIN/SILVER OR EQUIV" at 11663,3096.4 h60
  text "OTHER" at 13094.46,3092.47 h60
  text "ARRAY/PANEL:" at 11333.46,2937.09 h60
  text "CUT AND TRIM PER M1 BOARD OUTLINE" at 12394.46,2928.87 h60
  text "N.C. ROUTE" at 12394.46,2792.9 h60
  text "X" at 13082.46,2792.9 h60
  text "V. SCORE" at 13260.46,2792.9 h60
  text "CERTIFICATION:" at 11333.46,2663.77 h60
  text "MATERIALS AND WORKMANSHIP FOR ALL PCBS" at 12058.46,2663.77 h60
  text "TO MEET OR EXCEED THE REQUIREMENTS OF:" at 12058.46,2569.71 h60
  text "X" at 11695.97,2441.08 h60
  text "ANSI IPC-A-600F CLASS ->" at 11823.96,2441.08 h60
  text "X" at 13471.97,2441.08 h60
  text "2" at 13581.96,2441.08 h60
  text "1" at 13266.96,2439.58 h60
  text "3" at 13935.96,2439.58 h60
  text "X" at 12507.97,2293.39 h60
  text "RoHS" at 12635.96,2293.39 h60
  text "OTHER" at 13280.36,2293.39 h60
  text "PER ORDER" at 13677.42,2293.39 h60
  text "ALL BOARDS MUST MEET OR EXCEED UL94-V0 REQUIREMENTS." at 11361,2139.57 h60
  text "PCB MUST BEAR THE UL94V-0 UL REGISTERED MATERIAL ID NUMBER" at 11361,2023.5 h60
  text "ADDITIONAL REQUIREMENTS:" at 11333.46,1854.08 h60
  text "MICROSECTION:" at 11408.23,1746.95 h60
  text "YES" at 12313.96,1746.95 h60
  text "REQUIRED" at 13175.46,1602.62 h60
  text "BARE BOARD ELEC. TEST:" at 11408.23,1599.76 h60
  text "NONE" at 12713.96,1599.76 h60
  text "X" at 13057.46,1599.76 h60
  text "PER ORDER" at 13767.46,1599.76 h60
  text "XX MIL VIAS REQUIRE NON-CONDUCTIVE FILL AND PLANARIZE" at 11576.38,1394.82 h59
  text "XX MIL VIAS REQUIRE CONDUCTIVE FILL AND PLANARIZE" at 11584.38,1290.84 h60
  text "OUTER XX MIL TRACES REQUIRE 50 OHM SINGLE-ENDED IMPEDANCE" at 11583.39,1127.46 h58
  text "LAYER 2 & 3 (INNER LAYERS) XX MIL WIDE, XX MIL SPACE / TRACES REQUIRE 100 OHM DIFFERENTIAL IMPEDANCE" at 11575.39,891.74 h60
  text ".Layer_Name" at 577,-858.49 h60
M11 Gerber Information:
  lines w10: -292,-930.17 6308,-930.17 ; -292,-726.83 6310,-726.83 ; -292,-523.5 -292,-1133.5 3713,-1133.5 6310,-1133.5 6310,-523.5 -291.5,-523.5 -291.5,-1133.5 1284,-1133.5 ; 2173,-1133.5 2173,-523.5 ; 3440,-726.83 3440,-523.5 ; 4280,-726.83 4280,-523.5 ; 4902,-1140 4902,-937.17
  text "ALL ARTWORK VIEWED FROM TOP SIDE" at -228.5,-655.67 h60
  text "BOARD #:" at 2248,-655.67 h60
  text ".PRJ_Number" at 2793.5,-655.67 h60
  text "REV:" at 3638,-655.67 h60
  text ".PCB_Rev" at 3929.5,-655.67 h60
  text "SVN REV:" at 4476,-655.67 h60
  text ".VersionControl_RevNumber" at 4982,-655.67 h60
  text "LAYER NAME =" at -228.5,-858.49 h60
  text "TID #:" at 2248,-859 h60
  text ".TID" at 2793.5,-859 h60
  text "PLOT NAME =" at -228.5,-1064.34 h60
  text ".plot_File_Name" at 577,-1064.34 h60
  text "GENERATED    :" at 2250,-1064.34 h60
  text ".Print_Date" at 3119.5,-1064.34 h60
  text ".Print_Time" at 3848.5,-1064.34 h60
  text "TEXAS INSTRUMENTS" at 5113,-1064.34 h60
M12 Stackup:
  drawing of 295 lines, arcs and shapes, not listed
  text "Layer" at 9821.59,7874.94 h60
  text "Name" at 10231.51,7874.94 h60
  text "Material" at 11161.25,7874.94 h60
  text "Thickness" at 12021.02,7874.94 h60
  text "Constant" at 12670.85,7874.94 h60
  text "Board Layer Stack" at 13240.71,7874.94 h60
  text "Top Overlay" at 10231.51,7754.94 h60
  text "Top Solder" at 10231.51,7634.94 h60
  text "Solder Resist" at 11161.25,7634.94 h60
  text "0.40mil" at 12021.02,7634.94 h60
  text "3.5" at 12670.85,7634.94 h60
  text "1" at 9821.59,7514.94 h60
  text "Top Layer 1" at 10231.51,7514.94 h60
  text "CF-004" at 11161.25,7514.94 h60
  text "2.76mil" at 12021.02,7514.94 h60
  text "Core 1" at 10231.51,7394.94 h60
  text "PP-006" at 11161.25,7394.94 h60
  text "2.80mil" at 12021.02,7394.94 h60
  text "4.1" at 12670.85,7394.94 h60
  text "2" at 9821.59,7274.94 h60
  text "Inner Layer 2" at 10231.51,7274.94 h60
  text "2.76mil" at 12021.02,7274.94 h60
  text "Dielectric" at 10231.51,7154.94 h60
  text "FR-4 High Tg" at 11161.25,7154.94 h60
  text "59.20mil" at 12021.02,7154.94 h60
  text "4.8" at 12670.85,7154.94 h60
  text "3" at 9821.59,7034.94 h60
  text "Inner Layer 3" at 10231.51,7034.94 h60
  text "2.76mil" at 12021.02,7034.94 h60
  text "Core 2" at 10231.51,6914.94 h60
  text "PP-006" at 11161.25,6914.94 h60
  text "2.80mil" at 12021.02,6914.94 h60
  text "4.1" at 12670.85,6914.94 h60
  text "4" at 9821.59,6794.94 h60
  text "Bottom Layer 1" at 10231.51,6794.94 h60
  text "CF-004" at 11161.25,6794.94 h60
  text "2.76mil" at 12021.02,6794.94 h60
  text "Bottom Solder" at 10231.51,6674.94 h60
  text "Solder Resist" at 11161.25,6674.94 h60
  text "0.40mil" at 12021.02,6674.94 h60
  text "3.5" at 12670.85,6674.94 h60
  text "Bottom Overlay" at 10231.51,6554.94 h60
  text ".Layer_Name" at 577,-858.49 h60
M13 Component Bodies Top:
  text ".Layer_Name" at 577,-858.49 h60
M14 Component Bodies Bottom:
  text ".Layer_Name" at 577,-858.49 h60
M15 Courtyards Top:
  text ".Layer_Name" at 577,-858.49 h60
M16 Courtyards Bottom:
  text ".Layer_Name" at 577,-858.49 h60
Drill Drawing:
  circle w10: c6878.54,1082.98 r27.56
  lines w10: 6850.98,187.23 6850.98,201.02 6864.76,214.8 6850.98,228.58 6850.98,242.36 6864.76,242.36 6878.54,228.58 6892.32,242.36 6906.1,242.36 6906.1,228.58 6892.32,214.8 6906.1,201.02 6906.1,187.23 6892.32,187.23 6878.54,201.02 6864.76,187.23 6850.98,187.23 ; 6850.98,325.04 6864.76,325.04 6864.76,311.26 6892.32,311.26 6892.32,325.04 6906.1,325.04 6906.1,352.6 6892.32,352.6 6892.32,366.38 6864.76,366.38 6864.76,352.6 6850.98,352.6 6850.98,325.04 ; 6850.98,435.29 6878.54,449.07 6906.1,435.29 6892.32,462.85 6906.1,490.41 6878.54,476.63 6850.98,490.41 6864.76,462.85 6850.98,435.29 ; 6850.98,559.31 6906.1,559.31 6906.1,614.44 6850.98,614.44 6850.98,559.31 ; 6850.98,697.12 6864.76,697.12 6878.54,683.34 6892.32,697.12 6906.1,697.12 6892.32,710.9 6906.1,724.68 6892.32,724.68 6878.54,738.46 6864.76,724.68 6850.98,724.68 6864.76,710.9 6850.98,697.12 ; 6850.98,862.49 6906.1,862.49 6878.54,807.37 6850.98,862.49 ; 6850.98,958.96 6878.54,931.39 6906.1,958.96 6878.54,986.52 6850.98,958.96 ; 6850.98,1179.45 6906.1,1179.45 6906.1,1234.57 6850.98,1234.57 6850.98,1179.45 ; 6862,1190.47 6895.08,1190.47 6895.08,1223.55 6862,1223.55 6862,1190.47
  lines w12: 6801,150.03 10030.34,150.03 ; 6801,1266.27 10030.34,1266.27 ; 7138.36,26 7138.36,1390.29 ; 7440.23,26 7440.23,1390.29 ; 8028.53,26 8028.53,1390.29 ; 8287.33,26 8287.33,1390.29 ; 8662.08,26 8662.08,1390.29 ; 9464.53,26 9464.53,1390.29 ; 6801,26 10030.34,26 10030.34,1390.29 6801,1390.29 6801,26
  text "Symbol" at 6875.42,1303.47 h72
  text "Count" at 7175.57,1303.47 h72
  text "Hole Size" at 7477.43,1303.47 h72
  text "Plated" at 8065.74,1303.47 h72
  text "Hole Type" at 8324.54,1303.47 h72
  text "Drill Layer Pair" at 8699.29,1303.47 h72
  text "Hole Tolerance" at 9501.74,1303.47 h72
  text "23" at 7175.57,1179.45 h60
  text "7.87mil (0.200mm)" at 7477.43,1179.45 h60
  text "PTH" at 8065.74,1179.45 h60
  text "Round" at 8324.54,1179.45 h60
  text "Top Layer 1 - Bottom Layer 1" at 8699.29,1179.45 h60
  text "328" at 7175.57,1055.42 h60
  text "16.00mil (0.406mm)" at 7477.43,1055.42 h60
  text "PTH" at 8065.74,1055.42 h60
  text "Round" at 8324.54,1055.42 h60
  text "Top Layer 1 - Bottom Layer 1" at 8699.29,1055.42 h60
  text "32" at 7175.57,931.39 h60
  text "35.04mil (0.890mm)" at 7477.43,931.39 h60
  text "PTH" at 8065.74,931.39 h60
  text "Round" at 8324.54,931.39 h60
  text "Top Layer 1 - Bottom Layer 1" at 8699.29,931.39 h60
  text "31" at 7175.57,807.37 h60
  text "40.00mil (1.016mm)" at 7477.43,807.37 h60
  text "PTH" at 8065.74,807.37 h60
  text "Round" at 8324.54,807.37 h60
  text "Top Layer 1 - Bottom Layer 1" at 8699.29,807.37 h60
  text "3" at 7175.57,683.34 h60
  text "40.16mil (1.020mm)" at 7477.43,683.34 h60
  text "PTH" at 8065.74,683.34 h60
  text "Round" at 8324.54,683.34 h60
  text "Top Layer 1 - Bottom Layer 1" at 8699.29,683.34 h60
  text "2" at 7175.57,559.31 h60
  text "49.21mil (1.250mm)" at 7477.43,559.31 h60
  text "PTH" at 8065.74,559.31 h60
  text "Round" at 8324.54,559.31 h60
  text "Top Layer 1 - Bottom Layer 1" at 8699.29,559.31 h60
  text "2" at 7175.57,435.29 h60
  text "50.00mil (1.270mm)" at 7477.43,435.29 h60
  text "PTH" at 8065.74,435.29 h60
  text "Round" at 8324.54,435.29 h60
  text "Top Layer 1 - Bottom Layer 1" at 8699.29,435.29 h60
  text "8" at 7175.57,311.26 h60
  text "61.81mil (1.570mm)" at 7477.43,311.26 h60
  text "PTH" at 8065.74,311.26 h60
  text "Round" at 8324.54,311.26 h60
  text "Top Layer 1 - Bottom Layer 1" at 8699.29,311.26 h60
  text "8" at 7175.57,187.23 h60
  text "128.00mil (3.251mm)" at 7477.43,187.23 h60
  text "PTH" at 8065.74,187.23 h60
  text "Round" at 8324.54,187.23 h60
  text "Top Layer 1 - Bottom Layer 1" at 8699.29,187.23 h60
  text "437 Total" at 7175.57,63.21 h60
  text ".Layer_Name" at 577,-858.49 h60
M17 Embedded Cavity:
  text ".Layer_Name" at 577,-858.49 h60
M18 Embedded Assembly:
  text ".Layer_Name" at 577,-858.49 h60
M19 Embedded Keepout:
  text ".Layer_Name" at 577,-858.49 h60

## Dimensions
0,4250 to 6500,0 on M2 Board Dimensions
0,-400 to 1000,-400 on M2 Board Dimensions
6500,0 to 0,4250 on M2 Board Dimensions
